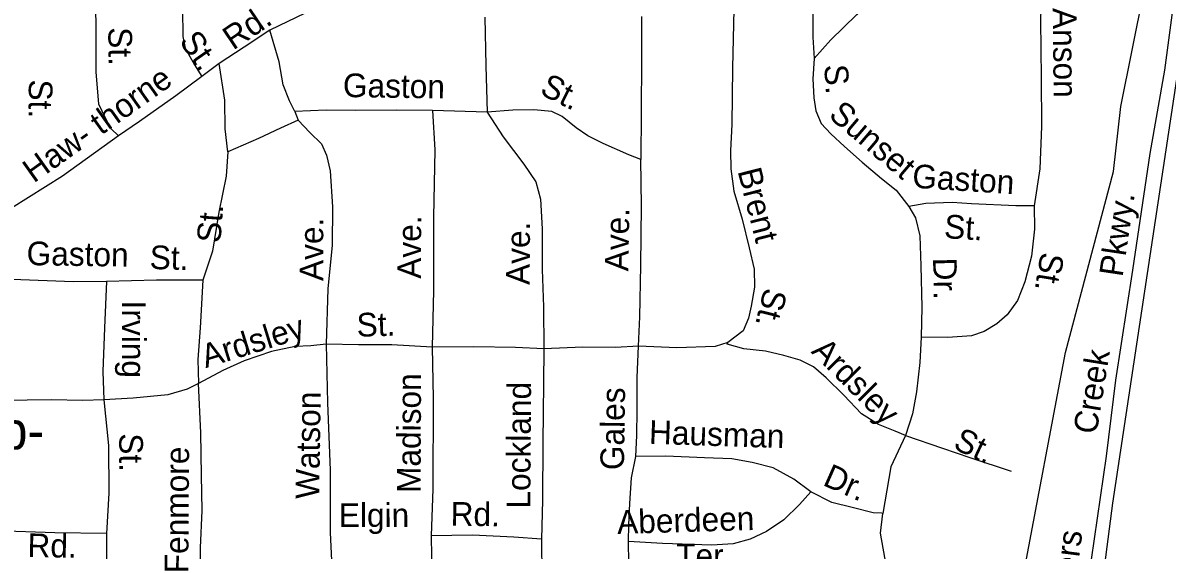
# Model space of a CAD drawing. Extents: x 1547597 to 1699558, y 810033 to 920809.
# Drawn here: x 1623759 to 1628353, y 849529 to 851645 of the extents above; entities that cross this region are included whole.
import ezdxf

# ---------------------------------------------------------------- set-up
doc = ezdxf.new("R2010")
doc.units = 0
for name, color, linetype in [('Exist Cultural Church Label', 7, 'Continuous'), ('Exist Hydrographic Creek Single Shore', 7, 'Continuous'), ('Exist Road Non-System Type 51', 7, 'Continuous'), ('Exist Road Non-System Type 51 Label', 7, 'Continuous'), ('Exist Road Primary NC UnDivided 4 Lane Attributed', 7, 'Continuous')]:
    doc.layers.add(name, color=color, linetype=linetype)

msp = doc.modelspace()

# ---------------------------------------------------------------- linework, layer by layer
at = {"layer": 'Exist Hydrographic Creek Single Shore'}
msp.add_lwpolyline([(1627775.8, 849423), (1627945.8, 850322.2), (1628138.5, 851049), (1628167.8, 851309.1), (1628259.6, 851768.9), (1628324.5, 852110.2), (1628292.1, 852417.7), (1628080.1, 852711.3), (1627545.9, 853515.8), (1627511.4, 853606.3), (1627501.9, 853671), (1627519.4, 853773.6), (1627534, 853831.4), (1627196, 854056.3), (1626798.6, 854418.4)], dxfattribs=at)
at = {"layer": 'Exist Road Non-System Type 51'}
for p, q in [((1624892.8, 851684.3), (1624750.4, 851616)), ((1624548, 851481.8), (1624477.5, 851429.4)), ((1624850.8, 851289.1), (1624864.3, 851255)), ((1625623.7, 851286), (1625404.3, 851292.9))]:
    msp.add_line(p, q, dxfattribs=at)
for points in [[(1624393.2, 852209.5), (1624391.2, 852079.6), (1624390.1, 851869.7), (1624399.5, 851699.7), (1624401.8, 851589.8), (1624411.1, 851543.5), (1624448, 851477.2), (1624477.5, 851429.4)], [(1624143.7, 851191.9), (1624114.1, 851219.2), (1624091.4, 851262.4), (1624064.1, 851319.3), (1624054, 851448.9), (1624053, 851658.9), (1624035.1, 851877.4), (1624025.7, 852036.9), (1624019.5, 852183.9)], [(1626618.5, 852040.5), (1626612.7, 851918.5), (1626613.4, 851698.6), (1626607.9, 851465), (1626606.3, 851237.1), (1626600.7, 851133.1), (1626601.6, 851059.3), (1626614.2, 850969.1), (1626646.6, 850856.6), (1626674.7, 850742.4), (1626695.3, 850656.1), (1626696.3, 850584.1), (1626683.1, 850508.3), (1626672.3, 850460.5), (1626651.7, 850408.9), (1626589.1, 850361.7)], [(1627847.5, 852049.5), (1627851.2, 851902.2), (1627845.6, 851654.4), (1627847.9, 851424.4), (1627848.9, 851228.5), (1627842.5, 851058.7), (1627820.3, 850911.1)], [(1626931.7, 851999.7), (1626929.5, 851863.9), (1626931.1, 851705.9), (1626931.3, 851588.1), (1626936, 851501.9)], [(1627228.7, 851963.2), (1627217.5, 851881.6), (1627200.3, 851807.9), (1627173.6, 851754.2), (1627106.4, 851677.4), (1627003.2, 851577), (1626936, 851501.9)], [(1625613.5, 851668), (1625618.5, 851472), (1625623.7, 851286)], [(1626243.2, 851670.3), (1626242.6, 851500.4), (1626241.4, 851284.5), (1626240.6, 851096.6)], [(1624750.4, 851616), (1624648.1, 851547.7), (1624548, 851481.8)], [(1624850.8, 851289.1), (1624829.4, 851331.5), (1624804.3, 851395.9), (1624787.8, 851488.1), (1624750.4, 851616)], [(1626936, 851501.9), (1626930.7, 851420.2), (1626935.6, 851344), (1626942.7, 851292.1), (1626964.1, 851241.8), (1627003.3, 851199.2), (1627058.5, 851148.4), (1627129.5, 851085.4), (1627206.4, 851020.2), (1627265.7, 850973.3), (1627316.6, 850908.7)], [(1624582.5, 851127.2), (1624572, 851219.3), (1624569.8, 851335.4), (1624548, 851481.8)], [(1624477.5, 851429.4), (1624372.9, 851352.1), (1624227.8, 851248.8), (1624143.7, 851191.9)], [(1625404.3, 851292.9), (1625258.5, 851295), (1625094.6, 851293.5), (1624976.8, 851295.3), (1624850.8, 851289.1)], [(1625404.3, 851292.9), (1625413.9, 851134.8), (1625407.7, 850865.2), (1625407.3, 850571.4), (1625401.9, 850343.6)], [(1626240.6, 851096.6), (1626192.8, 851115.4), (1626089.6, 851160.7), (1626027.6, 851191.6), (1625980.7, 851223.9), (1625924.7, 851269.1), (1625883.7, 851289.7), (1625810.2, 851295.8), (1625726.6, 851295.3), (1625623.7, 851286)], [(1625623.7, 851286), (1625688.1, 851187.2), (1625770.4, 851077.9), (1625819.2, 851007.3), (1625838.2, 850937.1), (1625844.4, 850819.1), (1625843.8, 850655.2), (1625849.6, 850505.2), (1625851, 850337.3)], [(1624864.3, 851255), (1624793.8, 851222), (1624705.3, 851181.4), (1624582.5, 851127.2)], [(1624864.3, 851255), (1624911.5, 851204.4), (1624958.6, 851159.6), (1624977.9, 851113.4), (1624993, 851051.3), (1625002.7, 850907.2), (1625000.4, 850753.4), (1624984.2, 850578.2), (1624977.3, 850355.2)], [(1624143.7, 851191.9), (1623918.6, 851030.3), (1623713.3, 850901.2)], [(1624582.5, 851127.2), (1624575, 851029.5), (1624545.7, 850885.4), (1624520.7, 850728.4), (1624482.1, 850612.4)], [(1626231.2, 850347.2), (1626237, 850464.9), (1626240, 850670.8), (1626243.6, 850910.6), (1626240.6, 851096.6)], [(1627820.3, 850911.1), (1627746.2, 850910.2), (1627568.5, 850919), (1627490.8, 850923.9), (1627384.8, 850919.7), (1627316.6, 850908.7)], [(1627316.6, 850908.7), (1627343.8, 850862.3), (1627360.8, 850790.1), (1627365, 850670.2), (1627368.4, 850504.2), (1627366.6, 850384.2)], [(1627820.3, 850911.1), (1627820.8, 850817.2), (1627809.2, 850709.4), (1627781.7, 850605.9), (1627752.5, 850530.4), (1627711.8, 850473), (1627669.2, 850437.7), (1627618.8, 850406.5), (1627568.6, 850389.3), (1627472.6, 850382.6), (1627366.6, 850384.2)], [(1624095.5, 850607.8), (1623961.3, 850605.5), (1623716.8, 850614.5)], [(1624095.5, 850607.8), (1624086.4, 850421.2), (1624079.6, 850246), (1624084.1, 850132.3)], [(1624482.1, 850612.4), (1624416.1, 850612.4), (1624295.6, 850612.4), (1624095.5, 850607.8)], [(1624482.1, 850612.4), (1624470.7, 850421.2), (1624461.6, 850293.8), (1624463.9, 850198.2)], [(1624977.3, 850355.2), (1624915.9, 850348.4), (1624852.3, 850346.1), (1624757.2, 850325.7), (1624648.1, 850289.3), (1624561.6, 850250.6), (1624463.9, 850198.2)], [(1624977.3, 850355.2), (1624981.9, 850120.9), (1624992.7, 849850), (1624993, 849600.1), (1625001.8, 849404), (1624999, 849204.1), (1624998.6, 849058.2), (1625004.2, 848900.2)], [(1625401.9, 850343.6), (1625240.7, 850353), (1625106.9, 850353), (1624977.3, 850355.2)], [(1626589.1, 850361.7), (1626538.8, 850346.5), (1626385, 850340.8), (1626231.2, 850347.2)], [(1627302.7, 849989.8), (1627261, 850006.5), (1627195.1, 850033.9), (1627126.1, 850076.4), (1627055.3, 850150.8), (1626984.4, 850220), (1626933.3, 850264.7), (1626879.6, 850291.6), (1626814, 850310.5), (1626740.3, 850327.6), (1626654.6, 850336.8), (1626587, 850355.8), (1626589.1, 850361.7)], [(1627366.6, 850384.2), (1627361.1, 850282.4), (1627347.3, 850165), (1627331.4, 850076.4), (1627302.7, 849989.8)], [(1625401.9, 850343.6), (1625406.8, 850139.6), (1625405.2, 849775.8), (1625398.3, 849586)], [(1625851, 850337.3), (1625737.5, 850342.6), (1625569.6, 850345), (1625401.9, 850343.6)], [(1625851, 850337.3), (1625849, 850199.4), (1625847.4, 849961.5), (1625845.9, 849729.8), (1625841.5, 849573.8)], [(1626231.2, 850347.2), (1626139.1, 850342.6), (1626007, 850344.1), (1625851, 850337.3)], [(1626220.4, 849905.5), (1626223.7, 849989.5), (1626225.2, 850091.3), (1626225.3, 850221.4), (1626231.2, 850347.2)], [(1624463.9, 850198.2), (1624418.4, 850175.5), (1624341.1, 850152.7), (1624202.4, 850139.1), (1624084.1, 850132.3)], [(1624484.5, 848880), (1624475.6, 848964.2), (1624476.5, 849144.1), (1624471.2, 849330.1), (1624472.5, 849537.8), (1624478.7, 849687.7), (1624477, 849829.7), (1624473.4, 849999.6), (1624463.9, 850198.2)], [(1624084.1, 850132.3), (1624000, 850130), (1623872.6, 850132.3), (1623679.4, 850130)], [(1624084.1, 850132.3), (1624103, 849949.1), (1624104.1, 849757.2), (1624095.6, 849595.5)], [(1627302.7, 849989.8), (1627244.7, 849863.9), (1627212.4, 849676.8)], [(1627302.7, 849989.8), (1627451.7, 849938.3), (1627561.4, 849901.1), (1627727.7, 849846.2)], [(1626191.3, 849564.1), (1626192.2, 849630.2), (1626195.6, 849716.1), (1626203.1, 849819.8), (1626220.4, 849905.5)], [(1626923.5, 849763.2), (1626854.3, 849814.2), (1626771.2, 849859.3), (1626687.6, 849880.7), (1626605.9, 849895.9), (1626496.1, 849899.6), (1626340.3, 849905.7), (1626220.4, 849905.5)], [(1626923.5, 849763.2), (1626876.9, 849711.9), (1626814, 849651), (1626745.4, 849603.9), (1626678.9, 849572.9), (1626610.7, 849554), (1626524.8, 849549.2), (1626327, 849556.2), (1626191.3, 849564.1)], [(1627206.4, 849676.9), (1627173.9, 849678.7), (1627088.9, 849699.9), (1627006.9, 849719.9), (1626923.5, 849763.2)], [(1627247.9, 849385.9), (1627229, 849456.4), (1627219.9, 849499.8), (1627202.2, 849597.2), (1627212.4, 849676.8), (1627206.4, 849676.9)], [(1624095.6, 849595.5), (1623888, 849598.5), (1623652, 849606.3)], [(1624095.6, 849595.5), (1624095.4, 849447.6), (1624092.1, 849235.7), (1624088, 848951.9), (1624083.4, 848656.2), (1624074.1, 848436.4), (1624063.5, 848268.8), (1624058.4, 848055), (1624055.2, 847861.1)], [(1625841.5, 849573.8), (1625730, 849581.1), (1625564.3, 849589.5), (1625398.3, 849586)], [(1625398.3, 849586), (1625401.8, 849420.1), (1625399.8, 849286.2), (1625404.6, 849214.1), (1625411.5, 849138.1), (1625447.8, 849025.7), (1625467.8, 848899.4)], [(1625841.5, 849573.8), (1625843.3, 849423.9), (1625840.1, 849216.3), (1625841.3, 849032.3), (1625841.1, 848890.5)], [(1626704, 847939.4), (1626701.5, 848043.5), (1626693.3, 848147.6), (1626686.1, 848211.6), (1626655.5, 848288), (1626612.5, 848358.7), (1626533.9, 848449.8), (1626475.3, 848530.6), (1626450.1, 848589), (1626438.9, 848641), (1626439.7, 848687), (1626401.4, 849061.4), (1626384.4, 849129.6), (1626310.2, 849240.6), (1626245.9, 849345.5), (1626220.8, 849397.9), (1626192, 849478.3), (1626191.3, 849564.1)]]:
    msp.add_lwpolyline(points, dxfattribs=at)
at = {"layer": 'Exist Road Primary NC UnDivided 4 Lane Attributed'}
for points in [[(1628401.1, 853586.7), (1628382.9, 853545.1), (1628364.8, 853484.7), (1628352, 853390.7), (1628351.2, 853354.9), (1628350.8, 853274.7), (1628352.2, 853232.5), (1628354.6, 853170.7), (1628352.4, 852816.7), (1628369.5, 852349.6), (1628379.9, 852005.9), (1628371.8, 851676.4), (1628343.2, 851454.6), (1628283.9, 851120.2), (1628215.1, 850653.1), (1628145.8, 850211.8), (1628109.1, 849906.7), (1628036, 849408.8)], [(1628213.2, 847090.1), (1628205.5, 847181.5), (1628173.3, 847582.8), (1628154.4, 847785.4), (1628143.6, 847928.5), (1628130.1, 848145.2), (1628111.2, 848380.1), (1628085.3, 848744.8), (1628076.4, 848873.9), (1628076.2, 849079.5), (1628080.3, 849236), (1628094.2, 849398.3), (1628135.8, 849717.6), (1628381.4, 851347.6), (1628428.5, 851658.8), (1628437.9, 852403.8), (1628398.8, 853218.1)]]:
    msp.add_lwpolyline(points, dxfattribs=at)

# ---------------------------------------------------------------- texts
at = {"layer": 'Exist Cultural Church Label'}
msp.add_text('Redemp-', height=150, dxfattribs=at).set_placement((1623019.6, 849933.8))
at = {"layer": 'Exist Road Non-System Type 51 Label'}
for s, rotation, p in [('Rd.', 34.1271, (1624603.6, 851533.3)), ('Anson', 270.5828, (1627894.3, 851704.3)), ('St.', 270.2579, (1624102.4, 851627.3)), ('St.', 304.9275, (1624384, 851571.3)), ('Haw- thorne', 35.3661, (1623802.6, 851000.1)), ('S.', 273.6513, (1626976.5, 851475.7)), ('St.', 269.3672, (1623783.4, 851418.2)), ('Gaston', 359.1519, (1625043.7, 851347.4)), ('St.', 333.2775, (1625830.2, 851361.3)), ('Sunset', 319.7154, (1626990.1, 851268)), ('Brent', 284.2726, (1626628.5, 851050.8)), ('Gaston', 356.3368, (1627328.3, 850983.7)), ('Pkwy.', 81.5352, (1628174.3, 850622.8)), ('St.', 85.6585, (1624552.1, 850759.9)), ('Ave.', 89.9309, (1625358.2, 850618.1)), ('Ave.', 89.1247, (1626190.4, 850647.4)), ('St.', 356.3368, (1627456.2, 850781.7)), ('Ave.', 89.9059, (1624965, 850609.1)), ('Ave.', 89.8165, (1625794.4, 850593.2)), ('Gaston', 359.1185, (1623773.6, 850672.9)), ('St.', 358.3668, (1624267.5, 850657.5)), ('St.', 260.6448, (1627846.9, 850728.1)), ('Dr.', 271.1857, (1627413.5, 850702)), ('St.', 255.8211, (1626737, 850585.9)), ('Irving', 269.9641, (1624157.1, 850530.7)), ('Ardsley', 17.1903, (1624493.2, 850259.2)), ('St.', 1.5803, (1625100.5, 850385.4)), ('Ardsley', 315.0726, (1626920.8, 850323.4)), ('Creek', 80.8132, (1628069.8, 849991)), ('Madison', 89.7514, (1625355.9, 849758.4)), ('Lockland', 89.6089, (1625796.4, 849695.7)), ('Gales', 89.1749, (1626172.5, 849849.7)), ('Watson', 89.1362, (1624948.8, 849734)), ('Hausman', 358.107, (1626272.1, 849956.2)), ('St.', 269.916, (1624146.3, 849998.1)), ('St.', 334.7619, (1627490, 849938.6)), ('Fenmore', 89.6693, (1624423.6, 849436.1)), ('Dr.', 336.1755, (1626966.8, 849791.4)), ('Elgin', 0.1775, (1625028.1, 849621.7)), ('Rd.', 359.169, (1625476.1, 849627.7)), ('Aberdeen', 1.6236, (1626146.5, 849594.2)), ('Rd.', 359.169, (1623777.3, 849501.4)), ('Peters', 82.6785, (1627966.9, 849239.2)), ('Ter.', 359.6289, (1626381.9, 849460.2))]:
    msp.add_text(s, height=95, rotation=rotation, dxfattribs=at).set_placement(p)

doc.saveas('drawing.dxf')
